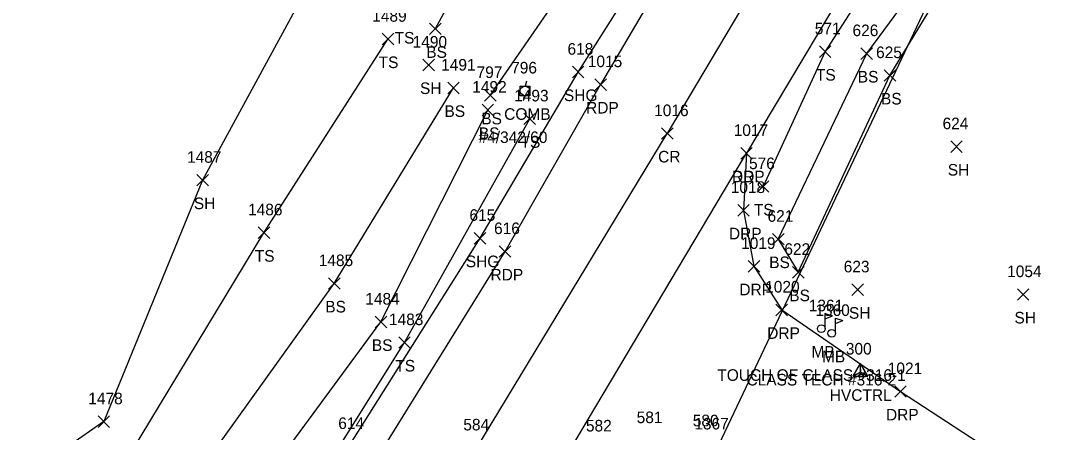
# Model space of a CAD drawing. Extents: x 1639430 to 1640195, y 612006 to 612917.
# Drawn here: x 1639665.7 to 1639843.9, y 612444.1 to 612515.2 of the extents above; entities that cross this region are included whole.
import ezdxf

# ---------------------------------------------------------------- set-up
doc = ezdxf.new("R2010")
doc.units = 0
for name, color, linetype in [('C_A', 7, 'Continuous'), ('C_I', 7, 'Continuous'), ('CPSM', 7, 'Continuous'), ('DCP', 7, 'Continuous'), ('L_A', 7, 'Continuous'), ('L_C', 7, 'Continuous'), ('L_I', 7, 'Continuous'), ('L_TIC', 7, 'Continuous'), ('LELB', 7, 'Continuous'), ('LMB', 7, 'Continuous'), ('LSOGP', 7, 'Continuous'), ('P_A', 7, 'Continuous'), ('P_I', 7, 'Continuous'), ('P_TIC', 7, 'Continuous'), ('PET', 7, 'Continuous'), ('PRC', 7, 'Continuous'), ('PSU', 7, 'Continuous'), ('R_A', 7, 'Continuous'), ('R_I', 7, 'Continuous'), ('R_TIC', 7, 'Continuous'), ('RDP', 7, 'Continuous'), ('U_A', 7, 'Continuous'), ('U_C', 7, 'Continuous'), ('U_I', 7, 'Continuous'), ('UP', 7, 'Continuous')]:
    doc.layers.add(name, color=color, linetype=linetype)

msp = doc.modelspace()

# ---------------------------------------------------------------- linework, layer by layer
at = {"layer": 'CPSM'}
for p, q in [((1639809.52, 612453.83), (1639810.77, 612455.99)), ((1639812.02, 612453.83), (1639810.77, 612455.99)), ((1639810.77, 612454.55), (1639810.77, 612455.99)), ((1639809.52, 612453.83), (1639810.77, 612454.55)), ((1639809.52, 612453.83), (1639812.02, 612453.83)), ((1639810.77, 612454.55), (1639810.77, 612454.55)), ((1639810.77, 612454.55), (1639812.02, 612453.83))]:
    msp.add_line(p, q, dxfattribs=at)
at = {"layer": 'DCP'}
msp.add_lwpolyline([(1639836.53, 612547.97), (1639769.19, 612405.95)], dxfattribs=at)
at = {"layer": 'L_TIC'}
for points in [[(1639736.3, 612512.75), (1639738.3, 612514.75)], [(1639738.3, 612512.75), (1639736.3, 612514.75)], [(1639728.12, 612510.98), (1639730.12, 612512.98)], [(1639730.12, 612510.98), (1639728.12, 612512.98)], [(1639803.67, 612508.82), (1639805.67, 612510.82)], [(1639805.67, 612508.82), (1639803.67, 612510.82)], [(1639810.85, 612508.49), (1639812.85, 612510.49)], [(1639812.85, 612508.49), (1639810.85, 612510.49)], [(1639735.17, 612506.51), (1639737.17, 612508.51)], [(1639737.17, 612506.51), (1639735.17, 612508.51)], [(1639814.86, 612504.7), (1639816.86, 612506.7)], [(1639816.86, 612504.7), (1639814.86, 612506.7)], [(1639739.45, 612502.55), (1639741.45, 612504.55)], [(1639741.45, 612502.55), (1639739.45, 612504.55)], [(1639745.81, 612501.27), (1639747.81, 612503.27)], [(1639747.81, 612501.27), (1639745.81, 612503.27)], [(1639745.39, 612498.74), (1639747.39, 612500.74)], [(1639747.39, 612498.74), (1639745.39, 612500.74)], [(1639752.63, 612497.23), (1639754.63, 612499.23)], [(1639754.63, 612497.23), (1639752.63, 612499.23)], [(1639826.36, 612492.43), (1639828.36, 612494.43)], [(1639828.36, 612492.43), (1639826.36, 612494.43)], [(1639696.1, 612486.64), (1639698.1, 612488.64)], [(1639698.1, 612486.64), (1639696.1, 612488.64)], [(1639792.93, 612485.54), (1639794.93, 612487.54)], [(1639794.93, 612485.54), (1639792.93, 612487.54)], [(1639706.71, 612477.57), (1639708.71, 612479.57)], [(1639708.71, 612477.57), (1639706.71, 612479.57)], [(1639795.56, 612476.46), (1639797.56, 612478.46)], [(1639797.56, 612476.46), (1639795.56, 612478.46)], [(1639795.56, 612476.46), (1639797.56, 612478.46)], [(1639797.56, 612476.46), (1639795.56, 612478.46)], [(1639799.02, 612470.75), (1639801.02, 612472.75)], [(1639801.02, 612470.75), (1639799.02, 612472.75)], [(1639718.86, 612468.81), (1639720.86, 612470.81)], [(1639720.86, 612468.81), (1639718.86, 612470.81)], [(1639809.28, 612467.73), (1639811.28, 612469.73)], [(1639811.28, 612467.73), (1639809.28, 612469.73)], [(1639837.88, 612466.91), (1639839.88, 612468.91)], [(1639839.88, 612466.91), (1639837.88, 612468.91)], [(1639726.91, 612462.17), (1639728.91, 612464.17)], [(1639728.91, 612462.17), (1639726.91, 612464.17)], [(1639730.99, 612458.62), (1639732.99, 612460.62)], [(1639732.99, 612458.62), (1639730.99, 612460.62)], [(1639679.04, 612444.97), (1639681.04, 612446.97)], [(1639681.04, 612444.97), (1639679.04, 612446.97)]]:
    msp.add_lwpolyline(points, dxfattribs=at)
at = {"layer": 'LELB'}
for points in [[(1639873.78, 612630.16), (1639868.37, 612620.63), (1639857.45, 612600.97), (1639851.55, 612585.17), (1639842.17, 612567.76), (1639826.77, 612543.6), (1639823.11, 612538.52), (1639804.67, 612509.82), (1639793.93, 612486.54)], [(1639798.64, 612584.24), (1639790.64, 612587.03), (1639783.43, 612585.38), (1639768.31, 612566.18), (1639755.35, 612547.01), (1639737.3, 612513.75)], [(1639796.56, 612477.46), (1639811.85, 612509.49), (1639828.19, 612531.6), (1639834.27, 612547.92)], [(1639796.56, 612477.46), (1639800.02, 612471.75), (1639815.86, 612505.7), (1639830.7, 612530.15), (1639840.48, 612545.98)], [(1639746.81, 612502.27), (1639764.19, 612527.42)], [(1639693.1, 612406.13), (1639684.65, 612416.71), (1639683.14, 612437.98), (1639707.71, 612478.57), (1639729.12, 612511.98)], [(1639695.33, 612414.29), (1639688.55, 612417.67), (1639695.93, 612436.52), (1639719.86, 612469.81), (1639740.45, 612503.55)], [(1639695.33, 612414.29), (1639705.17, 612432.28), (1639727.91, 612463.17), (1639746.39, 612499.74)], [(1639693.1, 612406.13), (1639712.26, 612428.1), (1639731.99, 612459.62), (1639753.63, 612498.23)]]:
    msp.add_lwpolyline(points, dxfattribs=at)
at = {"layer": 'LMB'}
for p, q in [((1639804.65, 612464.61), (1639805.95, 612464.23)), ((1639804.66, 612462.02), (1639804.66, 612464.61)), ((1639804.66, 612463.71), (1639805.94, 612464.22)), ((1639806.45, 612463.81), (1639807.74, 612463.43)), ((1639806.45, 612461.22), (1639806.45, 612463.81)), ((1639806.45, 612462.91), (1639807.74, 612463.42)), ((1639804, 612462.01), (1639804, 612462.01)), ((1639805.8, 612461.21), (1639805.8, 612461.21))]:
    msp.add_line(p, q, dxfattribs=at)
for centre in [(1639804, 612462.01), (1639805.8, 612461.21)]:
    msp.add_circle(centre, 0.656, dxfattribs=at)
at = {"layer": 'LSOGP'}
msp.add_lwpolyline([(1639717.74, 612525.52), (1639714.82, 612520.27), (1639697.1, 612487.64), (1639680.04, 612445.97), (1639644.57, 612421.3), (1639635.96, 612403.52), (1639624.25, 612382.3), (1639608.49, 612348.06), (1639600.03, 612336.44), (1639596.7, 612332.58), (1639605.32, 612321.89), (1639618.65, 612314.53), (1639630.7, 612306.67)], dxfattribs=at)
at = {"layer": 'P_TIC'}
for points in [[(1639760.99, 612505.29), (1639762.99, 612507.29)], [(1639762.99, 612505.29), (1639760.99, 612507.29)], [(1639764.87, 612503.14), (1639766.87, 612505.14)], [(1639766.87, 612503.14), (1639764.87, 612505.14)], [(1639776.38, 612494.69), (1639778.38, 612496.69)], [(1639778.38, 612494.69), (1639776.38, 612496.69)], [(1639790.07, 612491.27), (1639792.07, 612493.27)], [(1639792.07, 612491.27), (1639790.07, 612493.27)], [(1639744.05, 612476.62), (1639746.05, 612478.62)], [(1639746.05, 612476.62), (1639744.05, 612478.62)], [(1639748.36, 612474.33), (1639750.36, 612476.33)], [(1639750.36, 612474.33), (1639748.36, 612476.33)]]:
    msp.add_lwpolyline(points, dxfattribs=at)
at = {"layer": 'PET'}
for points in [[(1639860.19, 612668.9), (1639846.37, 612644.49), (1639830.05, 612614.56), (1639810.07, 612579.97), (1639792.17, 612548.77), (1639765.87, 612504.14)], [(1639889.96, 612664.78), (1639871.04, 612630.27), (1639855.32, 612602.07), (1639833.92, 612564.51), (1639815.5, 612533.18), (1639791.07, 612492.27)], [(1639749.36, 612475.33), (1639765.87, 612504.14)], [(1639757.28, 612435.5), (1639791.07, 612492.27)], [(1639571.61, 612204.8), (1639581.27, 612221.94), (1639610.12, 612263.74), (1639636.18, 612301.91), (1639636.72, 612305.17), (1639674.04, 612358.08), (1639681.53, 612370.21), (1639706.2, 612406.33), (1639726.2, 612437.98), (1639749.36, 612475.33)]]:
    msp.add_lwpolyline(points, dxfattribs=at)
at = {"layer": 'PRC'}
for points in [[(1639858.8, 612637.72), (1639842.59, 612608.57), (1639822.13, 612572.44), (1639804.17, 612540.71), (1639777.38, 612495.69)], [(1639744.51, 612441.45), (1639777.38, 612495.69)]]:
    msp.add_lwpolyline(points, dxfattribs=at)
at = {"layer": 'PSU'}
msp.add_lwpolyline([(1639699.99, 612405.47), (1639722.39, 612441.7), (1639745.05, 612477.62), (1639761.99, 612506.29), (1639774.94, 612526.73)], dxfattribs=at)
at = {"layer": 'R_TIC'}
for points in [[(1639790.07, 612491.27), (1639792.07, 612493.27)], [(1639792.07, 612491.27), (1639790.07, 612493.27)], [(1639789.56, 612481.42), (1639791.56, 612483.42)], [(1639791.56, 612481.42), (1639789.56, 612483.42)], [(1639791.35, 612471.77), (1639793.35, 612473.77)], [(1639793.35, 612471.77), (1639791.35, 612473.77)], [(1639796.16, 612464.25), (1639798.16, 612466.25)], [(1639798.16, 612464.25), (1639796.16, 612466.25)], [(1639816.68, 612450.17), (1639818.68, 612452.17)], [(1639818.68, 612450.17), (1639816.68, 612452.17)]]:
    msp.add_lwpolyline(points, dxfattribs=at)
at = {"layer": 'RDP'}
msp.add_lwpolyline([(1639791.07, 612492.27), (1639790.56, 612482.42), (1639792.35, 612472.77), (1639797.16, 612465.25), (1639817.68, 612451.17), (1639836.4, 612438.97), (1639858.15, 612425.17), (1639868.59, 612420.18), (1639882.11, 612420.19), (1639897.25, 612425.27), (1639908.83, 612433.43), (1639923.77, 612450.11), (1639940.54, 612474.05), (1639946.23, 612483.43), (1639977.68, 612473.21), (1640001.7, 612464.66), (1640045.39, 612450.23), (1640094.56, 612433.69), (1640113.57, 612427.07)], dxfattribs=at)
at = {"layer": 'UP'}
for p, q in [((1639751.99, 612502.22), (1639751.99, 612503.88)), ((1639751.99, 612503.88), (1639753.66, 612503.88)), ((1639753.07, 612504.72), (1639752.82, 612503.88)), ((1639753.66, 612503.88), (1639753.66, 612502.22)), ((1639753.66, 612502.22), (1639751.99, 612502.22)), ((1639752.57, 612501.38), (1639752.82, 612502.22)), ((1639752.82, 612503.05), (1639752.82, 612503.05))]:
    msp.add_line(p, q, dxfattribs=at)
msp.add_circle((1639752.82, 612503.05), 0.833, dxfattribs=at)

# ---------------------------------------------------------------- texts
at = {"layer": 'C_A'}
msp.add_text('HVCTRL', height=2, dxfattribs=at).set_placement((1639805.46, 612449.55))
at = {"layer": 'C_I'}
msp.add_text('300', height=2, dxfattribs=at).set_placement((1639808.24, 612457.55))
at = {"layer": 'L_A'}
for s, p in [('TS', (1639730.28, 612511.21)), ('BS', (1639735.75, 612508.75)), ('TS', (1639727.52, 612506.98)), ('TS', (1639803.07, 612504.82)), ('BS', (1639810.3, 612504.49)), ('SH', (1639734.66, 612502.51)), ('BS', (1639814.31, 612500.7)), ('BS', (1639738.89, 612498.55)), ('BS', (1639745.25, 612497.27)), ('BS', (1639744.83, 612494.74)), ('TS', (1639752.04, 612493.23)), ('SH', (1639825.85, 612488.43)), ('SH', (1639695.59, 612482.64)), ('TS', (1639792.34, 612481.54)), ('TS', (1639706.12, 612473.57)), ('BS', (1639795, 612472.46)), ('BS', (1639795, 612472.46)), ('BS', (1639798.46, 612466.75)), ('BS', (1639718.3, 612464.81)), ('SH', (1639808.77, 612463.73)), ('SH', (1639837.37, 612462.91)), ('BS', (1639726.35, 612458.17)), ('MB', (1639802.31, 612457.01)), ('MB', (1639804.11, 612456.21)), ('TS', (1639730.4, 612454.62))]:
    msp.add_text(s, height=2, dxfattribs=at).set_placement(p)
at = {"layer": 'L_C'}
for s, p in [('TOUCH OF CLASS #316-1', (1639786.03, 612453.01)), ('CLASS TECH #316-2', (1639791.07, 612452.21))]:
    msp.add_text(s, height=2, dxfattribs=at).set_placement(p)
at = {"layer": 'L_I'}
for s, p in [('1489', (1639726.41, 612514.98)), ('571', (1639802.87, 612512.82)), ('626', (1639809.39, 612512.49)), ('1490', (1639733.39, 612510.51)), ('625', (1639813.46, 612508.7)), ('1491', (1639738.32, 612506.55)), ('797', (1639744.44, 612505.27)), ('1492', (1639743.69, 612502.74)), ('1493', (1639750.93, 612501.23)), ('624', (1639824.95, 612496.43)), ('1487', (1639694.41, 612490.64)), ('576', (1639791.51, 612489.54)), ('1486', (1639704.96, 612481.57)), ('621', (1639794.71, 612480.46)), ('621', (1639794.71, 612480.46)), ('622', (1639797.61, 612474.75)), ('1485', (1639717.17, 612472.81)), ('623', (1639807.87, 612471.73)), ('1054', (1639836.11, 612470.91)), ('1484', (1639725.21, 612466.17)), ('1361', (1639801.83, 612465.01)), ('1360', (1639802.97, 612464.21)), ('1483', (1639729.3, 612462.62)), ('1478', (1639677.35, 612448.97))]:
    msp.add_text(s, height=2, dxfattribs=at).set_placement(p)
at = {"layer": 'P_A'}
for s, p in [('SHG', (1639759.53, 612501.29)), ('RDP', (1639763.36, 612499.14)), ('CR', (1639775.81, 612490.69)), ('RDP', (1639788.56, 612487.27)), ('SHG', (1639742.58, 612472.62)), ('RDP', (1639746.85, 612470.33))]:
    msp.add_text(s, height=2, dxfattribs=at).set_placement(p)
at = {"layer": 'P_I'}
for s, p in [('618', (1639760.15, 612509.29)), ('1015', (1639763.66, 612507.14)), ('1016', (1639775.12, 612498.69)), ('1017', (1639788.86, 612495.27)), ('615', (1639743.21, 612480.62)), ('616', (1639747.46, 612478.33)), ('614', (1639720.54, 612444.7)), ('584', (1639742.15, 612444.45))]:
    msp.add_text(s, height=2, dxfattribs=at).set_placement(p)
at = {"layer": 'R_A'}
for p in [(1639788.56, 612487.27), (1639788.04, 612477.42), (1639789.84, 612467.77), (1639794.65, 612460.25), (1639815.17, 612446.17)]:
    msp.add_text('DRP', height=2, dxfattribs=at).set_placement(p)
at = {"layer": 'R_I'}
for s, p in [('1017', (1639788.86, 612495.27)), ('1018', (1639788.35, 612485.42)), ('1019', (1639790.14, 612475.77)), ('1020', (1639794.3, 612468.25)), ('1021', (1639815.48, 612454.17)), ('582', (1639763.33, 612444.27)), ('581', (1639772.1, 612445.71)), ('580', (1639781.79, 612445.16)), ('1367', (1639782.06, 612444.62))]:
    msp.add_text(s, height=2, dxfattribs=at).set_placement(p)
at = {"layer": 'U_A'}
msp.add_text('COMB', height=2, dxfattribs=at).set_placement((1639749.21, 612498.05))
at = {"layer": 'U_C'}
msp.add_text('#4/342/60', height=2, dxfattribs=at).set_placement((1639744.78, 612494.05))
at = {"layer": 'U_I'}
msp.add_text('796', height=2, dxfattribs=at).set_placement((1639750.41, 612506.05))

doc.saveas('drawing.dxf')
